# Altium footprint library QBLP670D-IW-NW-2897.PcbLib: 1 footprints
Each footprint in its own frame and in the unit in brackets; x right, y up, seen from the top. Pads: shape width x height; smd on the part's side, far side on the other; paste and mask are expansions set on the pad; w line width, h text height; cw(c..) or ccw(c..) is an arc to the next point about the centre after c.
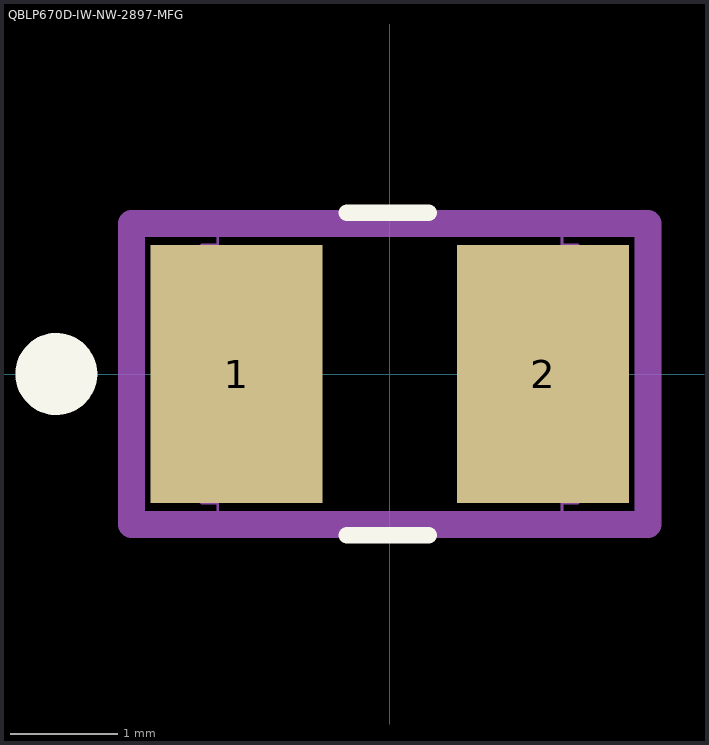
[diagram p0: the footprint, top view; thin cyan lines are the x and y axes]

## QBLP670D-IW-NW-2897-MFG [mm]
pads (2):
  rect 1.6x2.4 smd paste+0 mask+0: 1(-1.425,0) 2(1.425,0)
Top Overlay:
  circle w0.381: c-3.1,0 r0.191
  lines w0.152: -0.4,-1.5 0.362,-1.5 ; -0.4,1.5 0.362,1.5
Mechanical 5:
  lines w0.25: -2.4,-1.4 -2.4,1.4 2.4,1.4 2.4,-1.4 -2.4,-1.4
Mechanical 13:
  lines w0.025: -1.6,-1.2 -1.75,-1.2 -1.75,1.2 -1.6,1.2 ; 1.6,-1.2 1.75,-1.2 1.75,1.2 1.6,1.2 ; -1.6,-1.4 -1.6,1.4 1.6,1.4 1.6,-1.4 -1.6,-1.4
Mechanical 15:
  lines w0.25: -2.4,-1.4 2.4,-1.4 2.4,1.4 -2.4,1.4 -2.4,-1.4
3D body "QBLP670D.step": height 3.6, standoff 0, extent -1.75,-1.4 1.75,1.4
